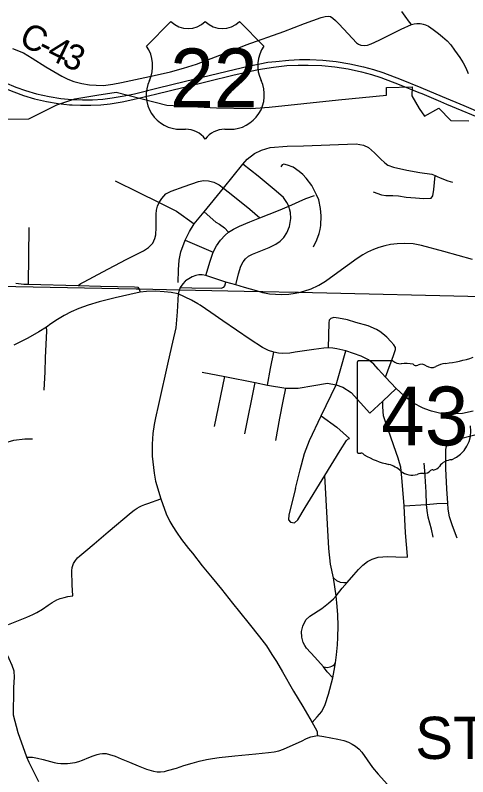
# Model space of a CAD drawing. Extents: x 2402298 to 2498138, y 789485 to 950881.
# Drawn here: x 2476688 to 2482051, y 865555 to 874577 of the extents above; entities that cross this region are included whole.
import ezdxf

# ---------------------------------------------------------------- set-up
doc = ezdxf.new("R2010")
doc.units = 0
for name, color, linetype in [('GM_X_City_Street', 7, 'Continuous'), ('GM_X_Corporation', 7, 'Continuous'), ('GM_X_Corporation_Text', 7, 'Continuous'), ('GM_X_County_Road', 7, 'Continuous'), ('GM_X_County_Road_Text', 7, 'Continuous'), ('GM_X_State_Route', 7, 'Continuous'), ('GM_X_State_Shield', 7, 'Continuous'), ('GM_X_Township', 7, 'Continuous'), ('GM_X_Township_Road', 7, 'Continuous'), ('GM_X_US_Route', 7, 'Continuous'), ('GM_X_US_Shield', 7, 'Continuous')]:
    doc.layers.add(name, color=color, linetype=linetype)

msp = doc.modelspace()

# ---------------------------------------------------------------- linework, layer by layer
at = {"layer": 'GM_X_City_Street'}
for p, q in [((2476844.4, 871392.4), (2476855.1, 872062.6)), ((2478703, 871912.3), (2479031.9, 871768.1)), ((2479050.4, 869704.3), (2479170.7, 870297.8)), ((2479408.4, 869616.9), (2479531.5, 870224.4)), ((2480889.9, 869862.9), (2481043.9, 870005.8))]:
    msp.add_line(p, q, dxfattribs=at)
for points in [[(2478619.7, 871408.8), (2478622.4, 871561.7), (2478631.1, 871675.5), (2478652, 871771.8), (2478703, 871912.3), (2478751.7, 872015.6), (2478808.2, 872104.5), (2478928.8, 872245.9), (2479155.4, 872529.8), (2479386.1, 872813), (2479438.6, 872870.9), (2479522.8, 872936.9), (2479607, 872978.7), (2479708, 873008.3), (2479909.4, 873024.5), (2480103.4, 873030.5), (2480729.7, 873054.1), (2480816.6, 873037.9), (2480873.1, 873009.7), (2480947.2, 872945), (2481015.3, 872875), (2481067.8, 872827.1), (2481102.8, 872802.2), (2481170.2, 872777.3), (2481327.8, 872739.6), (2481482, 872712), (2481626.4, 872692.8), (2481665.7, 872676.1), (2481697.3, 872661.8), (2481716.5, 872653.8)], [(2479301.2, 871382.1), (2479332.7, 871511.3), (2479360.4, 871603.9), (2479387.7, 871654.7), (2479416.5, 871691.1), (2479452.2, 871720.7), (2479500, 871745.7), (2479698.7, 871826.1), (2479775.4, 871862.6), (2479828.5, 871899.7), (2479873.2, 871942.2), (2479907.4, 871998.4), (2479940, 872072.7), (2479953.7, 872169.8), (2479949.1, 872240.4), (2479939.2, 872284.8), (2479929.4, 872315.5), (2479907.8, 872359.5), (2479866, 872416.4), (2479781.8, 872492.3), (2479567.1, 872668.3), (2479386.1, 872813)], [(2480224.1, 871833), (2480263.2, 871917.2), (2480289.7, 871990.8), (2480303.4, 872038.2), (2480310.6, 872084.5), (2480312.9, 872199.4), (2480307.2, 872286.7), (2480285.2, 872389.8), (2480260.2, 872449.8), (2480204, 872557.9), (2480136.5, 872646.7), (2480097.4, 872690.3), (2480051.5, 872724.4), (2479981.3, 872774.9), (2479915.3, 872798.8), (2479870.2, 872811.3), (2479850.5, 872804.1), (2479834.5, 872780.9)], [(2480930.4, 872486.2), (2481028.7, 872449.4), (2481078.4, 872439.5), (2481163.4, 872439.9), (2481229, 872435.4), (2481321.5, 872419.8), (2481430.8, 872414.9), (2481526.8, 872406.5), (2481616.3, 872408.8), (2481638.3, 872438.4), (2481650.4, 872511.2), (2481665.7, 872676.1)], [(2481716.5, 872653.8), (2481745.3, 872641.9), (2481816, 872616.3), (2481871.3, 872598.8)], [(2477433.7, 871376.3), (2477465.5, 871398.2), (2477503.7, 871419.5), (2477727.3, 871537.9), (2478001.6, 871683.1), (2478207.7, 871787.4), (2478268.3, 871823.8), (2478316.8, 871877.7), (2478344.4, 871930.9), (2478353.8, 871976), (2478357.2, 872060.2), (2478359.9, 872219.1), (2478361.9, 872267.6), (2478373.3, 872312.8), (2478393.5, 872358.6), (2478423.8, 872407.1), (2478473, 872458.9), (2478534.3, 872493.3), (2478690.5, 872547.8), (2478859.6, 872607.7), (2478919.7, 872618.2), (2478979, 872613.4), (2479041.3, 872599), (2479105.2, 872566.8), (2479155.4, 872529.8), (2479268.6, 872439.2), (2479467.6, 872278.6), (2479585.1, 872175.2)], [(2477871.1, 872613), (2478144.9, 872480.3), (2478393.5, 872358.6), (2478599.5, 872254.7), (2478808.2, 872104.5)], [(2478945.8, 871492.7), (2478998.1, 871664.5), (2479031.9, 871768.1), (2479073.6, 871845.9), (2479120.2, 871912.6), (2479177.9, 871971), (2479217, 872004.8), (2479276.5, 872043.9), (2479347.5, 872078.8), (2479470, 872129.6), (2479585.1, 872175.2), (2479806.5, 872265), (2479929.4, 872315.5), (2480130.8, 872404.3), (2480234.7, 872441.1)], [(2478928.8, 872245.9), (2479066.8, 872126.6), (2479108.2, 872103.2), (2479166.5, 872056.8), (2479217, 872004.8)], [(2476696.9, 871403.9), (2476791.8, 871389.7), (2476844.4, 871392.4), (2477433.7, 871376.3), (2477700.4, 871366.8), (2478101.1, 871360.8), (2478139.5, 871353.4), (2478157, 871329.8), (2478168.3, 871295.7)], [(2478643.8, 871352.6), (2478782.2, 871348.9), (2479129, 871344.8), (2479160.1, 871353.5), (2479173.4, 871372.5), (2479185.5, 871414.8)], [(2481077, 870290.3), (2481172.5, 870546.4), (2481194.2, 870617.7), (2481193.8, 870639.3), (2481174.1, 870673), (2481138.4, 870712.5), (2481091, 870763), (2481045.5, 870803.9), (2481009.8, 870831.2), (2480969.6, 870854), (2480869.1, 870896.5), (2480726.5, 870937.8), (2480624.4, 870967), (2480519.3, 870989), (2480462.8, 870994.3), (2480426.4, 870984.5), (2480410.5, 870965.9), (2480403.4, 870933.9), (2480397.9, 870635.3)], [(2477030.9, 870135.7), (2477041, 870353.9), (2477047.7, 870518.3), (2477063.2, 870839.5), (2477058.5, 870882.9)], [(2479677.8, 870194.1), (2479713.9, 870390.3), (2479752.4, 870584)], [(2480008.5, 868970.1), (2480065.4, 869190.1), (2480116.2, 869385.9), (2480176.9, 869537.6), (2480314.4, 869831.7), (2480490.5, 870198.5), (2480547, 870392), (2480606.4, 870599)], [(2478903, 870348), (2479170.7, 870297.8), (2479531.5, 870224.4), (2479677.8, 870194.1), (2479895.2, 870159.6), (2480040.3, 870160.5), (2480227, 870188.5), (2480390.6, 870218.6), (2480490.5, 870198.5), (2480570.8, 870168.9), (2480667.4, 870106.1), (2480889.9, 869862.9)], [(2479776.3, 869536.8), (2479823.1, 869804.3), (2479862.8, 870003.4), (2479895.2, 870159.6)], [(2480314.4, 869831.7), (2480498.6, 869695), (2480650.2, 869563.5)], [(2481927.4, 868381.7), (2481870.5, 868526.6), (2481835.6, 868633.2), (2481820.5, 868723.8), (2481814.4, 868796.7), (2481803.4, 868967.7), (2481789.7, 869206.3), (2481791.6, 869433.4), (2481797.1, 869469.2), (2481808.7, 869497.9), (2481822.7, 869512.8), (2481840.2, 869525.9), (2481863.5, 869536.6), (2481885.7, 869543.8), (2482168.3, 869613.9)], [(2476144.9, 869252.6), (2476172.2, 869252.9), (2476220, 869260.4), (2476260.4, 869280.2), (2476326.4, 869346.2), (2476383, 869401.8), (2476462.2, 869460), (2476564.5, 869510.9), (2476671.6, 869543.6), (2476800.9, 869557.4), (2476892.2, 869557.4)], [(2480008.5, 868970.1), (2479929.6, 868657.5), (2479928, 868599.8), (2479949.3, 868570.3), (2479996.3, 868561.9), (2480038.8, 868599.1), (2480125.3, 868744), (2480357.3, 869125.2), (2480537.3, 869421.9), (2480612, 869537.2), (2480630.1, 869554), (2480650.2, 869563.5)], [(2481641.9, 868392), (2481619.9, 868488.3), (2481582.7, 868631.7), (2481570.6, 868708.7), (2481564, 868781.5), (2481556.5, 868927.2), (2481541.8, 869178.7), (2481535.7, 869268.3)], [(2480491.9, 867700.5), (2480458.4, 867910.2), (2480424.2, 868073.3), (2480404.5, 868259.2), (2480357.3, 869125.2)], [(2481296.3, 868766.6), (2481564, 868781.5), (2481685.4, 868791.7), (2481814.4, 868796.7)], [(2480458.4, 867910.2), (2480496.3, 867881.8), (2480537.3, 867860.9), (2480580.9, 867856), (2480622.2, 867857)], [(2480451.4, 866726.6), (2480386.7, 866799.4), (2480341.4, 866855.7), (2480236.7, 866971.8), (2480139.6, 867080.5), (2480119.6, 867111.2), (2480101.3, 867146.7), (2480083.3, 867209.8), (2480080.5, 867276.7), (2480094.7, 867337.4), (2480132.8, 867412.4), (2480177.5, 867457.8), (2480322.2, 867549.2), (2480399.1, 867609.9), (2480458.5, 867664.8), (2480491.9, 867700.5)], [(2480341.4, 866855.7), (2480364.7, 866851.6), (2480386.2, 866850.9), (2480421.2, 866855.7), (2480441.5, 866863.8), (2480456.9, 866874), (2480470.5, 866886.9), (2480482.7, 866903.4)]]:
    msp.add_lwpolyline(points, dxfattribs=at)
at = {"layer": 'GM_X_Corporation'}
msp.add_lwpolyline([(2475844.1, 873336.5), (2476850.9, 873350), (2477180.7, 873515.5), (2477394.2, 873586.1), (2477656.7, 873630.6), (2477885.6, 873665.7), (2478484.6, 873510.8), (2479074.6, 873480), (2479479.6, 873469.9), (2479699.1, 873488.7), (2480520.8, 873573.4), (2481089.4, 873628), (2481087.6, 873722.2), (2481393.8, 873728.3), (2481388.1, 873619.8), (2481476.1, 873472.8), (2481539.9, 873379.1), (2481706.3, 873475.9), (2481850.4, 873329.2), (2482062.8, 873325.6)], dxfattribs=at)
at = {"layer": 'GM_X_County_Road'}
for p, q in [((2479301.2, 871382.1), (2479185.5, 871414.8)), ((2479352.2, 871367.1), (2479301.2, 871382.1)), ((2479403.3, 871352.1), (2479352.2, 871367.1))]:
    msp.add_line(p, q, dxfattribs=at)
for points in [[(2479316.8, 874182), (2479425.4, 874224.4), (2479872.7, 874384.9), (2480118.1, 874477.4), (2480313.1, 874551.4), (2480359.4, 874562.8), (2480397.7, 874563.9), (2480423.8, 874560.2), (2480450.6, 874543.1), (2480483, 874515.7), (2480522.5, 874475.9), (2480632.8, 874357.3), (2480734, 874248.2), (2480757.2, 874232.3), (2480784.9, 874220.9), (2480823.6, 874217.9), (2480862.8, 874223.6), (2480907.8, 874239.1), (2481002.4, 874282.4), (2481262.7, 874409.8), (2481385.2, 874467.6)], [(2481385.2, 874467.6), (2481417.8, 874474.4), (2481449.2, 874477.7), (2481470.8, 874478.8), (2481488.4, 874477.6), (2481507.2, 874474.9), (2481523.6, 874470.6), (2481551.9, 874461.2), (2481584, 874446.7), (2481614, 874427.9), (2481642.3, 874408.2), (2481703, 874360.7), (2481752.5, 874319.8), (2481805, 874272), (2481849, 874224.7), (2481895.6, 874163.8), (2481955.8, 874076.4), (2481996.8, 874010.9), (2482027.7, 873955), (2482056.1, 873887.9)], [(2476657.4, 874182.7), (2476784.9, 874129.2), (2476887.7, 874068.9), (2477049.6, 873966.5), (2477238.5, 873854.2), (2477311.4, 873820.4), (2477383.1, 873792.3), (2477476, 873767.7), (2477566.7, 873751.8), (2477647.5, 873746.1), (2477733.2, 873744.9), (2477846.6, 873759.3), (2477947.1, 873779.4), (2478333.7, 873863.3), (2478527.9, 873906.9), (2478682.3, 873947.9), (2478834.8, 873995.3), (2479010.8, 874062.4), (2479316.8, 874182)], [(2482109, 871683.6), (2481766, 871778.9), (2481501, 871850.6), (2481403.3, 871866.6), (2481295.6, 871872.3), (2481216.3, 871868.9), (2481136.9, 871858.9), (2481067, 871843.9), (2480996.2, 871824.5), (2480932, 871799.7), (2480863.2, 871768.1), (2480808.2, 871737.3), (2480741.8, 871695), (2480512.7, 871527.8), (2480366, 871423.2), (2480287.4, 871376.6), (2480273.2, 871369.9)], [(2479185.5, 871414.8), (2478945.8, 871492.7), (2478904, 871499.9), (2478865, 871501), (2478827.8, 871493.8), (2478785.3, 871479.4), (2478706.4, 871429.4), (2478703.1, 871426)], [(2478703.1, 871426), (2478673.4, 871396), (2478643.8, 871352.6), (2478632.5, 871317.3), (2478619, 871275.4)], [(2480273.2, 871369.9), (2480192.4, 871332.2), (2480105.6, 871302.3), (2480044.8, 871288.2), (2480006.5, 871279.4), (2479929.1, 871268.8), (2479844.1, 871264.5), (2479773.1, 871266.9), (2479703.3, 871274.1), (2479624.3, 871288.7), (2479597.4, 871296), (2479546.1, 871309.9), (2479403.3, 871352.1)], [(2478619, 871275.4), (2478606.9, 871061), (2478589.7, 870873.4), (2478551.3, 870704.4)], [(2478551.3, 870704.4), (2478500.2, 870479.2), (2478385.8, 869963.4), (2478350.7, 869809), (2478336, 869728.1), (2478320.1, 869621.2), (2478311.1, 869496.5), (2478311.1, 869352.2), (2478333, 869153), (2478350.7, 869056), (2478412.1, 868846.1)], [(2481043.9, 869963.1), (2481043.9, 870005.8), (2481202.4, 870154.4)], [(2481231.2, 869314.2), (2481229.7, 869319.2), (2481080.7, 869746.1), (2481052.5, 869829.5), (2481043.9, 869936.5), (2481043.9, 869963.1)], [(2481336.3, 868166.7), (2481314.7, 868443), (2481296.3, 868766.6), (2481274.9, 869051.1), (2481258, 869223.1), (2481231.2, 869314.2)], [(2476607.5, 867358.3), (2476826.8, 867447.4), (2476896.8, 867476.9), (2476945.7, 867500.1), (2477012.9, 867541.2), (2477078.1, 867589.9), (2477126.6, 867621.5), (2477179.6, 867649.2), (2477221.2, 867666), (2477267.5, 867680.2), (2477313.3, 867690.3), (2477368.8, 867697.7), (2477364.1, 867827.9), (2477357.7, 867993.4), (2477361.5, 868035.5), (2477379.2, 868082.8), (2477401.4, 868117.6), (2477426, 868147.3), (2477455.6, 868174.3), (2477526.4, 868230.9), (2477622.3, 868315.9), (2477791.1, 868458.6), (2478060.5, 868685.4), (2478098.3, 868713.6), (2478131.2, 868736.3), (2478160.6, 868752.6), (2478185.7, 868764.9), (2478222.7, 868780.6), (2478258.3, 868793.4), (2478412.1, 868846.1)], [(2478412.1, 868846.1), (2478477.8, 868669.4), (2478520.4, 868579.9), (2478554.6, 868521.8), (2478599.5, 868451.7), (2478660.1, 868365.3), (2478741.8, 868261)], [(2478741.8, 868261), (2478787.6, 868202.6), (2478905.4, 868054.6), (2479020.3, 867912.8), (2479130.7, 867777.1), (2479263, 867611.4), (2479346.5, 867507.1), (2479460.5, 867367), (2479581.2, 867214.3), (2479664.4, 867104.6), (2479730.4, 867005.5), (2479785.1, 866918.9), (2479854.3, 866800.1), (2479987.6, 866570.1), (2480095, 866387.7), (2480205.5, 866199.3), (2480257.4, 866109.1), (2480264.7, 866089.3), (2480267.5, 866065.2), (2480268.5, 866044.6)], [(2480491.9, 867700.5), (2480564.3, 867788.6), (2480622.2, 867857), (2480701.1, 867947.8), (2480756.3, 868010.9), (2480808.9, 868062.2), (2480861.6, 868103.7), (2480916.8, 868132.6), (2480989.2, 868158.3), (2481100.9, 868165.8), (2481198.5, 868161.4), (2481337.1, 868156.3), (2481336.3, 868166.7)], [(2480205.5, 866199.3), (2480265.7, 866266.7), (2480322.2, 866329.9), (2480361.7, 866411.4), (2480401.2, 866534.5), (2480451.4, 866726.6), (2480467, 866812.6), (2480482.7, 866903.4), (2480494.6, 866999.2), (2480507.7, 867117.8), (2480513, 867204.6), (2480515.2, 867345.1), (2480511.7, 867474.2), (2480503.8, 867571.6), (2480491.9, 867700.5)], [(2476823.8, 865786), (2476724.6, 866074.8), (2476667.2, 866286.8), (2476666.7, 866396.7), (2476673, 866484.1), (2476673.3, 866612.1), (2476678.5, 866736.8), (2476674.6, 866807.6), (2476650.9, 866874.9), (2476580.1, 867029.3), (2476573.1, 867045.5)], [(2476823.8, 865786), (2476859.4, 865787.7), (2476893.8, 865786), (2476953.6, 865774), (2477018.8, 865757.8), (2477151.3, 865725.2), (2477188.8, 865718), (2477228.6, 865713.3), (2477306.2, 865711.2), (2477399, 865723.6), (2477442, 865735), (2477485.8, 865749.9), (2477560.7, 865782.3), (2477612.2, 865803.9), (2477658.3, 865820.3), (2477691.5, 865827.5), (2477723.5, 865831.3), (2477764.9, 865829.1), (2477805.2, 865820.2), (2477870.9, 865798.1), (2477942.5, 865769.2), (2478042.4, 865727.7), (2478145.9, 865684.1), (2478242.7, 865646.6), (2478326.5, 865619.9), (2478369.8, 865613.1), (2478411.3, 865612.2), (2478456.8, 865618.1), (2478494.3, 865628.2), (2478598.4, 865658.9), (2478687.2, 865687.2), (2478784, 865715.1), (2478869.1, 865740), (2478955.1, 865761.2), (2479027.3, 865772.9), (2479106.2, 865783), (2479290.3, 865803.6), (2479539.7, 865827.6), (2479691.2, 865841.7), (2479756.9, 865852.2), (2479810.7, 865863.2), (2479867.1, 865881.3), (2479983.3, 865932), (2480081.5, 865978.6), (2480138.8, 866006.7), (2480192, 866027.3), (2480228.8, 866037.2), (2480268.5, 866044.6)], [(2480268.5, 866044.6), (2480346.2, 866031.3), (2480430, 866016.8), (2480512.7, 866000.8), (2480582.7, 865984.9), (2480637.1, 865965.2), (2480681.6, 865942.2), (2480721.3, 865917.9), (2480762.4, 865883.5), (2480793.8, 865844.7), (2480924, 865666), (2480987.6, 865587.3), (2481100.1, 865464.8), (2481132.2, 865432.8), (2481174.3, 865403.3), (2481216.6, 865380.5)], [(2476966.9, 865494.2), (2476851.2, 865722.6), (2476823.8, 865786)]]:
    msp.add_lwpolyline(points, dxfattribs=at)
at = {"layer": 'GM_X_State_Route'}
for points in [[(2478850.9, 871157.2), (2478778.3, 871200.4), (2478619, 871275.4), (2478536.6, 871290.9), (2478454.9, 871300.5), (2478353.9, 871307.2), (2478244, 871304.7), (2478168.3, 871295.7), (2478045.7, 871266.9), (2477873.2, 871227.2), (2477683.4, 871179.8), (2477550.6, 871141.3), (2477441.2, 871104.1), (2477349.9, 871064.4), (2477267.6, 871020.5), (2477188.3, 870973.7), (2477110.1, 870921.4), (2477058.5, 870882.9), (2476968.3, 870827.1), (2476836.8, 870749), (2476669.7, 870666.6)], [(2480990.7, 870383), (2480936.8, 870441), (2480874.5, 870493.8), (2480789.1, 870537.2), (2480606.4, 870599), (2480501.2, 870625.5), (2480453.9, 870632.7), (2480397.9, 870635.3), (2480344.6, 870633.4), (2480227.4, 870618), (2480006.6, 870583.1), (2479942.3, 870572.9), (2479860.1, 870568.5), (2479807.4, 870572.9), (2479752.4, 870584), (2479691.4, 870604.1), (2479619.2, 870640.3), (2479473.6, 870736.3), (2479312, 870846.3), (2479148.9, 870955), (2479005.5, 871054.8), (2478878.2, 871141), (2478850.9, 871157.2)], [(2481595.7, 869894.8), (2481522.7, 869921.9), (2481401.3, 869984.4), (2481296, 870068.4), (2481202.4, 870154.4), (2481077, 870290.3), (2480990.7, 870383)], [(2482114.5, 869887.6), (2481987.7, 869860), (2481829.1, 869850.4), (2481715.6, 869862.4), (2481620, 869885.8), (2481595.7, 869894.8)]]:
    msp.add_lwpolyline(points, dxfattribs=at)
at = {"layer": 'GM_X_State_Shield'}
for p, q in [((2481162.3, 870481), (2480754.6, 870481)), ((2480740.9, 870462.8), (2480740.9, 869406.1))]:
    msp.add_line(p, q, dxfattribs=at)
for centre, radius, start, end in [((2480756.8, 870465), 16.1, 98.1301, 188.1301), ((2481259.4, 870603.6), 156.4, 231.61951, 271.11188), ((2481637.1, 871921.5), 1476.4, 275.84447, 288.90645), ((2481311.2, 869887.7), 561.6, 80.48669, 94.98827), ((2481438.7, 870470.5), 45.1, 219.79206, 297.10237), ((2481505, 870348.4), 93.8, 54.46668, 119.14113), ((2481626.1, 870515.9), 112.9, 233.85621, 294.82819), ((2481825.4, 870158.2), 297, 97.34618, 120.76885), ((2481719.8, 869652.8), 369.3, 292.30889, 8.98584), ((2480757, 869403.8), 16.3, 171.95839, 258.30661), ((2480759.4, 869511.9), 124.2, 267.33899, 280.60386), ((2480784.8, 869345.2), 44.8, 29.74838, 93.27175), ((2481350.1, 870294.5), 1066.1, 240.41292, 257.1985), ((2481875.5, 869109.5), 202.2, 94.40312, 142.57675), ((2481032.2, 868931.4), 333.6, 47.18416, 75.83597), ((2481619.3, 869303.7), 119.3, 282.87319, 323.27711), ((2481393, 869339.9), 211.7, 230.70037, 286.29184), ((2481515.3, 868974.6), 173.9, 85.69512, 111.20995), ((2481530.8, 869260.8), 112.8, 268.77702, 315.54927), ((2481632.8, 869158.5), 31.8, 65.75173, 132.64842)]:
    msp.add_arc(centre, radius, start, end, dxfattribs=at)
at = {"layer": 'GM_X_Township'}
msp.add_lwpolyline([(2482386.8, 871237.3), (2480043.8, 871291.1), (2480003.7, 871292), (2479624.2, 871298.2), (2479596.4, 871298.9), (2478631.4, 871320.2), (2478481.9, 871323.4), (2478156.6, 871330.6), (2478122.4, 871331.4), (2475264.5, 871386.2)], dxfattribs=at)
at = {"layer": 'GM_X_Township_Road'}
msp.add_lwpolyline([(2481385.2, 874467.6), (2481360.3, 874495.4), (2481308.7, 874564.5), (2481271.6, 874619.5)], dxfattribs=at)
at = {"layer": 'GM_X_US_Route'}
for points in [[(2475288.7, 874783.2), (2475299.3, 874772.1), (2475512.2, 874552.9), (2475635.4, 874426.9), (2475814.5, 874243.6), (2475931.9, 874130.4), (2476047.7, 874029.7), (2476166.1, 873939.6), (2476282.5, 873862.4), (2476366.8, 873811.3), (2476543, 873720.9), (2476671.1, 873667.3), (2476786.9, 873624.4), (2476915.6, 873586.9), (2477057.6, 873553.6), (2477196.4, 873529.5), (2477329.4, 873516.7), (2477360.8, 873514.9)], [(2476566.4, 873779.4), (2476694.5, 873725.8), (2476810.3, 873682.9), (2476938.6, 873647.3), (2477089.2, 873613.3), (2477228.8, 873590.9), (2477358.9, 873578.1), (2477484.5, 873572.9), (2477605.6, 873574.2), (2477724.8, 873582.6), (2477835.6, 873596), (2477978.5, 873620.4), (2478102.8, 873647.3), (2478368.1, 873712.6), (2478707.7, 873795.3), (2479281.1, 873934.3), (2479447.1, 873973.4), (2479585.5, 874000.3), (2479681, 874018.9), (2479775.1, 874029.8), (2479932.1, 874043.9), (2480057.1, 874050.3), (2480180.1, 874050.3), (2480333.9, 874045.8), (2480492.1, 874027.9), (2480652.3, 874002.2), (2480813.5, 873965.2), (2480933, 873933), (2481044, 873898.7), (2481263.2, 873816.2), (2481493.7, 873720.2), (2481749.4, 873613.5), (2482005.1, 873505.8), (2482232.9, 873409.8)], [(2477360.8, 873514.9), (2477460.2, 873509.2), (2477583.5, 873509.7), (2477703.6, 873516.1), (2477812.9, 873528.5), (2477956, 873551), (2478083.1, 873578.8), (2478349.5, 873641.6), (2478690.4, 873724.7), (2479266.2, 873865.1), (2479566.3, 873933.2), (2479747, 873963.2), (2479906.2, 873979.3), (2480039.2, 873985.7), (2480158.7, 873986.8), (2480322.1, 873982), (2480475.5, 873966.4), (2480633.6, 873941), (2480790.1, 873906.7), (2480909.6, 873874.5), (2481020.6, 873840.2), (2481239.9, 873757.7), (2481470.4, 873661.7), (2481504.8, 873647.4)], [(2481504.8, 873647.4), (2481726.1, 873555.1), (2481798.4, 873524.6)], [(2481798.4, 873524.6), (2481981.8, 873447.3), (2482209.6, 873351.4), (2482377.5, 873281)]]:
    msp.add_lwpolyline(points, dxfattribs=at)
at = {"layer": 'GM_X_US_Shield'}
for p, q in [((2478533.6, 874501.3), (2478243.5, 874211.3)), ((2479635.7, 874211.3), (2479345.7, 874501.3)), ((2478649.6, 873225.1), (2478707.6, 873225.1)), ((2479171.7, 873225.1), (2479229.7, 873225.1))]:
    msp.add_line(p, q, dxfattribs=at)
for centre, radius, start, end in [((2478736.6, 874708.4), 290, 225.573, 314.427), ((2479142.7, 874708.4), 290, 225.573, 314.427), ((2477910.9, 873978.4), 406.1, 334.54712, 35.00093), ((2479968.3, 873978.4), 406.1, 144.99907, 205.45288), ((2478645.1, 873631.2), 406.1, 154.83192, 270.63826), ((2479234.2, 873631.2), 406.1, 269.36174, 25.16808), ((2478707.6, 872935.1), 290, 36.8699, 90), ((2479171.7, 872935.1), 290, 90, 143.1301)]:
    msp.add_arc(centre, radius, start, end, dxfattribs=at)

# ---------------------------------------------------------------- texts
at = {"layer": 'GM_X_Corporation_Text'}
msp.add_text('STEUBENVILLE', height=500, rotation=0.00001, dxfattribs=at).set_placement((2481429.4, 865766.3))
at = {"layer": 'GM_X_County_Road_Text'}
for s, rotation, p in [('C', 333.83237, (2476717.1, 874237.3)), ('4', 333.99168, (2477047.1, 874075.2)), ('-', 333.86146, (2476936.8, 874129.3)), ('3', 337.21189, (2477228.6, 873987.2))]:
    msp.add_text(s, height=300, rotation=rotation, dxfattribs=at).set_placement(p)
at = {"layer": 'GM_X_State_Shield'}
msp.add_text('43', height=696.1, dxfattribs=at).set_placement((2481024.2, 869480.7))
at = {"layer": 'GM_X_US_Shield'}
msp.add_text('22', height=696.1, dxfattribs=at).set_placement((2478523.7, 873486.2))

doc.saveas('drawing.dxf')
